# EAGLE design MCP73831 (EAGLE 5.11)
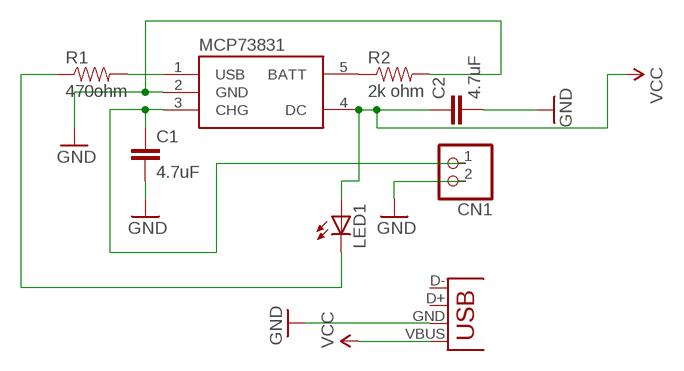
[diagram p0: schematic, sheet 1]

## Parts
C1  4.7uF  CAP0805  [0805]
C2  4.7uF  CAP0805  [0805]
CN1  JST_2PIN-THM  [JST-PH-2-THM]
LED1  LEDCHIP-LED0805  [CHIP-LED0805]
MCP73831  MAX1555  [SOT23-5]
R1  470ohm  RESISTOR  [0805]
R2  2k ohm  RESISTOR  [0805]
X1  USB-A-H  [USB-A-H]

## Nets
GND: C1.2 C2.2 CN1.2 MCP73831.2(GND) R2.2 X1.GND(VBUS)
N$1: MCP73831.5(BATT) R2.1
N$3: C1.1 CN1.1 MCP73831.3(CHG)
N$4: LED1.C R1.1
N$5: MCP73831.1(USB) R1.2
VCC: C2.1 LED1.A MCP73831.4(DC) X1.VBUS(GND)
Unconnected: X1.D+(D-) X1.D-(D+)

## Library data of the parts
C1 C2 = SparkFun:CAP: Capacitor
CN1 = adafruit:JST_2PIN: JST 2-Pin Connectors of various flavors
LED1 = adafruit:LED: LED
MCP73831 = SparkFun:MAX1555: MAX1555 Lithium Charger IC SOT-23 Lithium Polymer charging IC. Schematic element and footprint proven. Spark Fun Electronics SKU : COM-00674
R1 R2 = SparkFun:RESISTOR: Resistor
X1 = SparkFun:USB: USB Connectors USB-B-PTH is fully proven SKU : PRT-00139 USB-miniB is fully proven SKU : PRT-00587 USB-A-PCB is untested. USB-A-H is throughly reviewed, but untested. Spark Fun Electronics SKU : PRT-00437 USB-B-SMT is throughly reviewed, but untested. Needs silkscreen touching up. USB-A-S has not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

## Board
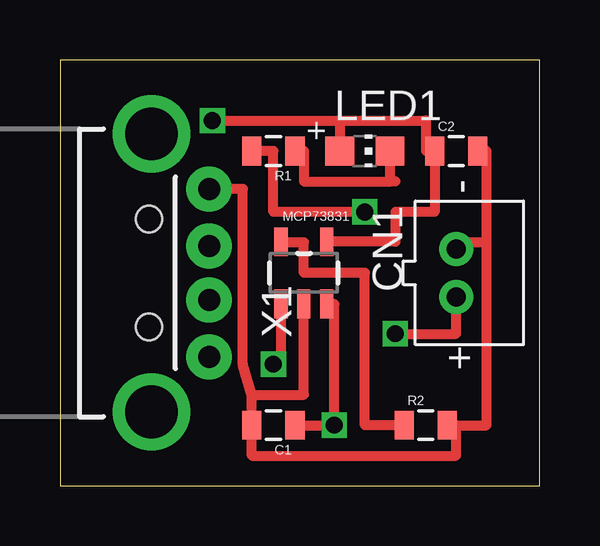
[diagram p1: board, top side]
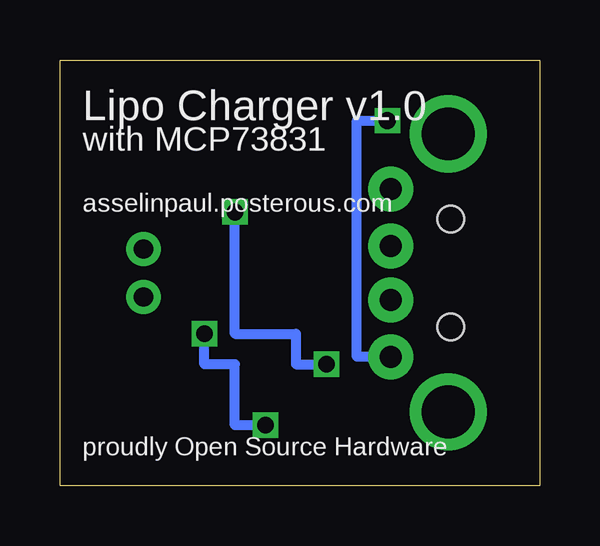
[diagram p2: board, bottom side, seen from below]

Size 19.99 x 17.77 mm. Coordinates in mm from the lower left corner, seen from the top.
Outline: 0,0 19.99,0 19.99,17.77 0,17.77 0,0
Copper layers (1*16): Top 0.0356mm / dielectric 1.5011mm / Bottom 0.0356mm
Design rules "Dorkbot-PDX": minimum track width 6mil, minimum drill 13mil, track to track 6mil, track to pad 6mil, pad to pad 6mil, via to via 6mil, smd to smd 6mil, copper to edge 15mil, drill to drill 6mil, minimum pad ring 7mil, minimum via ring 7mil, stop-mask expansion 4mil, vias tented up to drill 0mil, thermal gap 10mil

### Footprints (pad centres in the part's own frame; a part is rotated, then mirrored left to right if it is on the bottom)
0805 = smd 0.8 x 1.2: 1 -0.9,0; 2 0.9,0
JST-PH-2-THM = drill 0.8 pad 1.422 round: 1 1,0; 2 -1,0
CHIP-LED0805 = smd 1.2 x 1.2: A 0,-1.05; C 0,1.05
SOT23-5 = smd 0.55 x 1.2: 1 -0.95,-1.3; 2 0,-1.3; 3 0.95,-1.3; 4 0.95,1.3; 5 -0.95,1.3
USB-A-H = drill 0.914 pad 1.88 round: D+ 2.4,1.127; D- 2.4,-1.127; GND 2.4,3.5; VBUS 2.4,-3.5 | drill 2.2 round: GND@1 0,5.8; GND@2 0,-5.8 | hole 1.1: -0.1,2.25; -0.1,-2.25

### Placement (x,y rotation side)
C1  8.89,2.54 180 top
C2  16.51,13.97 0 top
CN1  16.51,8.89 270 top
LED1  12.7,13.97 270 top
MCP73831  10.16,8.89 0 top
R1  8.89,13.97 180 top
R2  15.24,2.54 0 top
X1  3.81,8.89 0 top

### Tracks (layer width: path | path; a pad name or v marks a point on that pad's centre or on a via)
GND
  Top 0.406: MCP73831.2 10.16,3.81 7.99,3.81 | 7.99,3.81 C1.2 7.99,1.27 16.51,1.27 16.51,2.54 R2.2 17.78,2.54 17.78,10.16 | 17.78,10.16 16.51,10.16 CN1.2 | C2.2 17.78,13.97 17.78,10.16 | X1.GND 7.62,12.39 7.62,5.08 7.99,3.81
N$1
  Top 0.406: R2.1 12.7,2.54 12.7,8.89 10.16,8.89 10.16,10.16 9.21,10.16 MCP73831.5
N$3  (via drill 0.7)
  Top 0.406: C1.1 v11.43,2.54 11.43,7.59 MCP73831.3 | v13.97,6.35 16.51,6.35 CN1.1
  Bottom 0.406: v11.43,2.54 12.7,2.54 12.7,5.08 13.97,5.08 v13.97,6.35
N$4
  Top 0.406: R1.1 10.16,13.97 10.16,12.7 13.75,12.7 | 13.97,12.7 13.75,12.7 | 13.75,12.7 LED1.C
N$5  (via drill 0.7)
  Top 0.406: R1.2 8.89,13.97 8.89,11.43 v12.7,11.43 | v8.89,5.08 9.21,5.08 MCP73831.1
  Bottom 0.406: v12.7,11.43 12.7,6.35 10.16,6.35 10.16,5.08 v8.89,5.08
VCC  (via drill 0.7)
  Top 0.406: v6.35,15.24 11.65,15.24 | 11.65,15.24 LED1.A | 11.65,15.24 15.24,15.24 15.24,13.97 C2.1 15.61,11.43 13.97,11.43 13.97,10.19 MCP73831.4
  Bottom 0.406: X1.VBUS 7.62,5.39 7.62,15.24 v6.35,15.24

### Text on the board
bPlace: Lipo Charger v1.0 | with MCP73831 | asselinpaul.posterous.com | proudly Open Source Hardware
